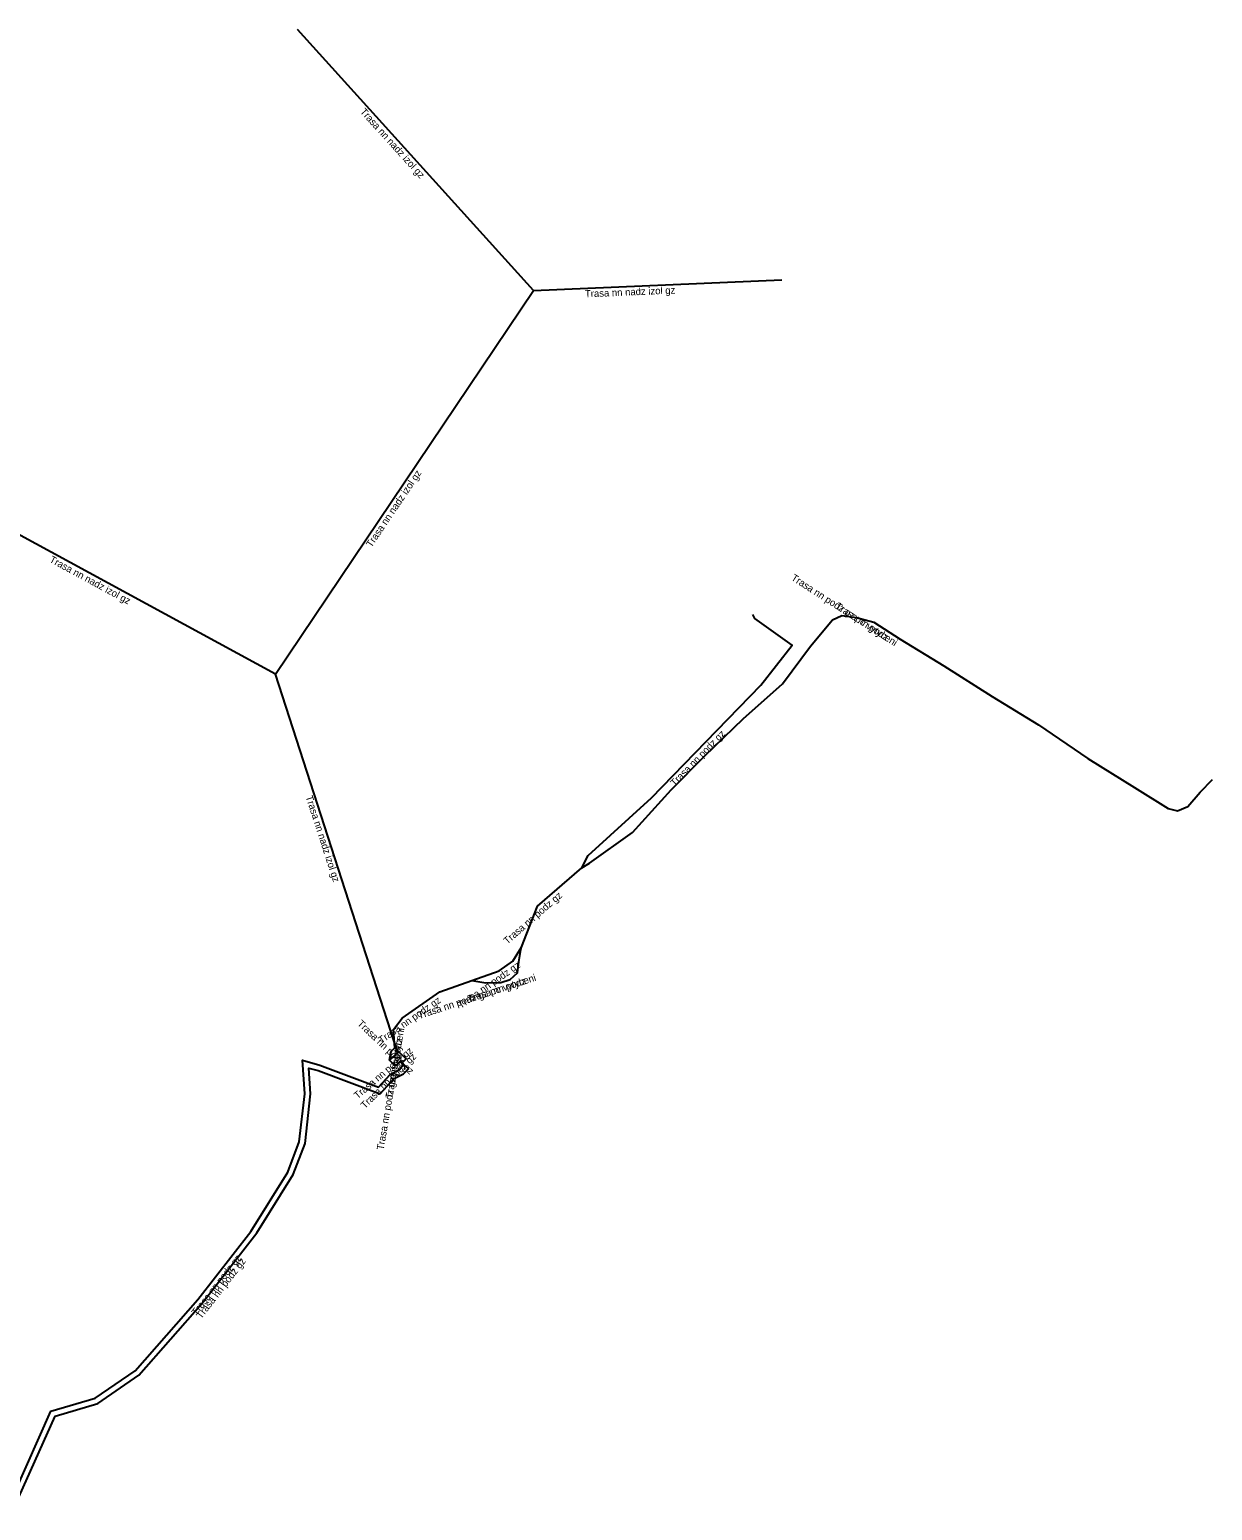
# Model space of a CAD drawing. Extents: x -724448 to -724084, y -973287 to -972828.
# Drawn here: x -724317.5 to -724234.3, y -972976.9 to -972872.8 of the extents above; entities that cross this region are included whole.
import ezdxf

# ---------------------------------------------------------------- set-up
doc = ezdxf.new("R2010")
doc.units = 0
doc.layers.add('Popiskový text - Ostatní atributy Trasy', color=7, linetype='Continuous')
doc.layers.add('Spojnice NN', color=7, linetype='Continuous')

msp = doc.modelspace()

# ---------------------------------------------------------------- linework, layer by layer
at = {"layer": 'Spojnice NN'}
for points in [[(-724282.09, -972891.1), (-724298.67, -972872.76)], [(-724300.22, -972918.07), (-724282.09, -972891.1)], [(-724282.09, -972891.1), (-724264.61, -972890.35)], [(-724300.22, -972918.07), (-724322.46, -972906.02)], [(-724278.68, -972931.69), (-724278.23, -972930.82), (-724273.79, -972926.77), (-724266.08, -972918.85), (-724263.89, -972916.05), (-724266.51, -972914.17), (-724266.66, -972913.89)], [(-724278.68, -972931.69), (-724278.14, -972931.38), (-724275.12, -972929.22), (-724272.4, -972926.21), (-724270.03, -972923.83), (-724267.34, -972921.22), (-724264.56, -972918.77), (-724262.6, -972916.12), (-724261.06, -972914.27), (-724260.39, -972913.95), (-724259.35, -972914.09), (-724258.15, -972914.42), (-724256.3, -972915.61), (-724253.22, -972917.49), (-724249.83, -972919.64), (-724246.56, -972921.65), (-724243.1, -972924.01), (-724239.81, -972926.04), (-724237.45, -972927.52), (-724236.79, -972927.68), (-724236.06, -972927.39), (-724235.19, -972926.38), (-724234.33, -972925.48)], [(-724278.68, -972931.69), (-724278.14, -972931.38), (-724275.12, -972929.22), (-724272.4, -972926.21), (-724270.03, -972923.83), (-724267.34, -972921.22), (-724264.56, -972918.77), (-724262.6, -972916.12), (-724261.06, -972914.27), (-724260.39, -972913.95), (-724259.35, -972914.09), (-724258.15, -972914.42), (-724256.3, -972915.61), (-724253.22, -972917.49), (-724249.83, -972919.64), (-724246.56, -972921.65), (-724243.1, -972924.01), (-724239.81, -972926.04), (-724237.45, -972927.52), (-724236.79, -972927.68), (-724236.06, -972927.39), (-724235.19, -972926.38), (-724234.33, -972925.48)], [(-724291.61, -972944.71), (-724300.22, -972918.07)], [(-724282.92, -972937.27), (-724281.79, -972934.39), (-724278.68, -972931.69)], [(-724286.42, -972939.62), (-724284.49, -972938.93), (-724283.54, -972938.26), (-724282.92, -972937.27)], [(-724286.42, -972939.62), (-724285.43, -972939.79), (-724284.38, -972939.76), (-724283.71, -972939.54), (-724283.21, -972939.08), (-724283.11, -972938.31), (-724282.98, -972937.46), (-724282.92, -972937.27)], [(-724286.42, -972939.62), (-724285.43, -972939.79), (-724284.38, -972939.76), (-724283.71, -972939.54), (-724283.21, -972939.08), (-724283.11, -972938.31), (-724282.98, -972937.46), (-724282.92, -972937.27)], [(-724291.83, -972944.35), (-724291.92, -972943.07), (-724291.32, -972942.27), (-724288.66, -972940.41), (-724286.42, -972939.62)], [(-724320.02, -972976.59), (-724318.59, -972975.66), (-724316.02, -972969.91), (-724312.9, -972968.99), (-724310.09, -972967.07), (-724305.69, -972962.05), (-724301.95, -972957.26), (-724299.35, -972953.09), (-724298.55, -972950.97), (-724298.17, -972947.59), (-724298.33, -972945.21), (-724297.1, -972945.57), (-724292.99, -972947.13), (-724292.17, -972946.23), (-724291.47, -972945.85), (-724291.23, -972945.5)], [(-724292.2, -972945.21), (-724292.09, -972944.59), (-724291.83, -972944.35)], [(-724292.2, -972945.21), (-724292.09, -972944.59), (-724291.83, -972944.35)], [(-724292.2, -972945.21), (-724291.61, -972944.71)], [(-724291.23, -972945.5), (-724291.23, -972945.61), (-724291.44, -972945.27), (-724291.79, -972945.61), (-724292.2, -972945.21)], [(-724291.23, -972945.5), (-724291.31, -972945.41), (-724291.03, -972945.12), (-724291.45, -972944.72), (-724291.83, -972944.35)], [(-724319.73, -972976.88), (-724318.27, -972975.94), (-724315.72, -972970.25), (-724312.72, -972969.35), (-724309.83, -972967.37), (-724305.39, -972962.31), (-724301.55, -972957.36), (-724298.99, -972953.27), (-724298.15, -972951.07), (-724297.77, -972947.59), (-724297.89, -972945.79), (-724297.23, -972945.95), (-724292.87, -972947.59), (-724291.89, -972946.51), (-724291.22, -972946.18), (-724290.88, -972945.83), (-724291.23, -972945.5)]]:
    msp.add_lwpolyline(points, dxfattribs=at)

# ---------------------------------------------------------------- texts
at = {"layer": 'Popiskový text - Ostatní atributy Trasy'}
for s, rotation, p in [('Trasa nn nadz izol gz', 312.1176, (-724294.31, -972878.56)), ('Trasa nn nadz izol gz', 2.4568, (-724278.45, -972891.59)), ('Trasa nn nadz izol gz', 56.0899, (-724293.48, -972909.21)), ('Trasa nn nadz izol gz', 331.5504, (-724316.17, -972910.17)), ('Trasa nn podz gz po vytyceni', 327.2491, (-724264, -972911.43)), ('Trasa nn podz', 327.2491, (-724260.9, -972913.43)), ('Trasa nn podz gz', 45.77, (-724272.15, -972926.01)), ('Trasa nn nadz izol gz', 287.9106, (-724298.11, -972926.7)), ('Trasa nn podz gz', 40.9502, (-724283.92, -972937.1)), ('Trasa nn podz gz', 35.0926, (-724287.19, -972941.62)), ('Trasa nn podz gz po vytyceni', 18.178, (-724290.12, -972942.33)), ('Trasa nn podz', 18.178, (-724286.62, -972941.18)), ('Trasa nn podz gz', 34.9978, (-724292.77, -972944.08)), ('Trasa nn podz gz', 316.3257, (-724294.51, -972942.7)), ('Trasa nn podz gz po vytyceni', 80.3574, (-724292.62, -972951.57)), ('Trasa nn podz', 80.3574, (-724292, -972947.94)), ('Trasa nn podz gz', 40.393, (-724294.45, -972947.98)), ('Trasa nn podz gz', 44.9173, (-724293.94, -972948.67)), ('Trasa nn podz gz', 52.044, (-724305.78, -972963.22)), ('Trasa nn podz gz', 52.1715, (-724305.45, -972963.45))]:
    msp.add_text(s, height=0.5, rotation=rotation, dxfattribs=at).set_placement(p)

doc.saveas('drawing.dxf')
